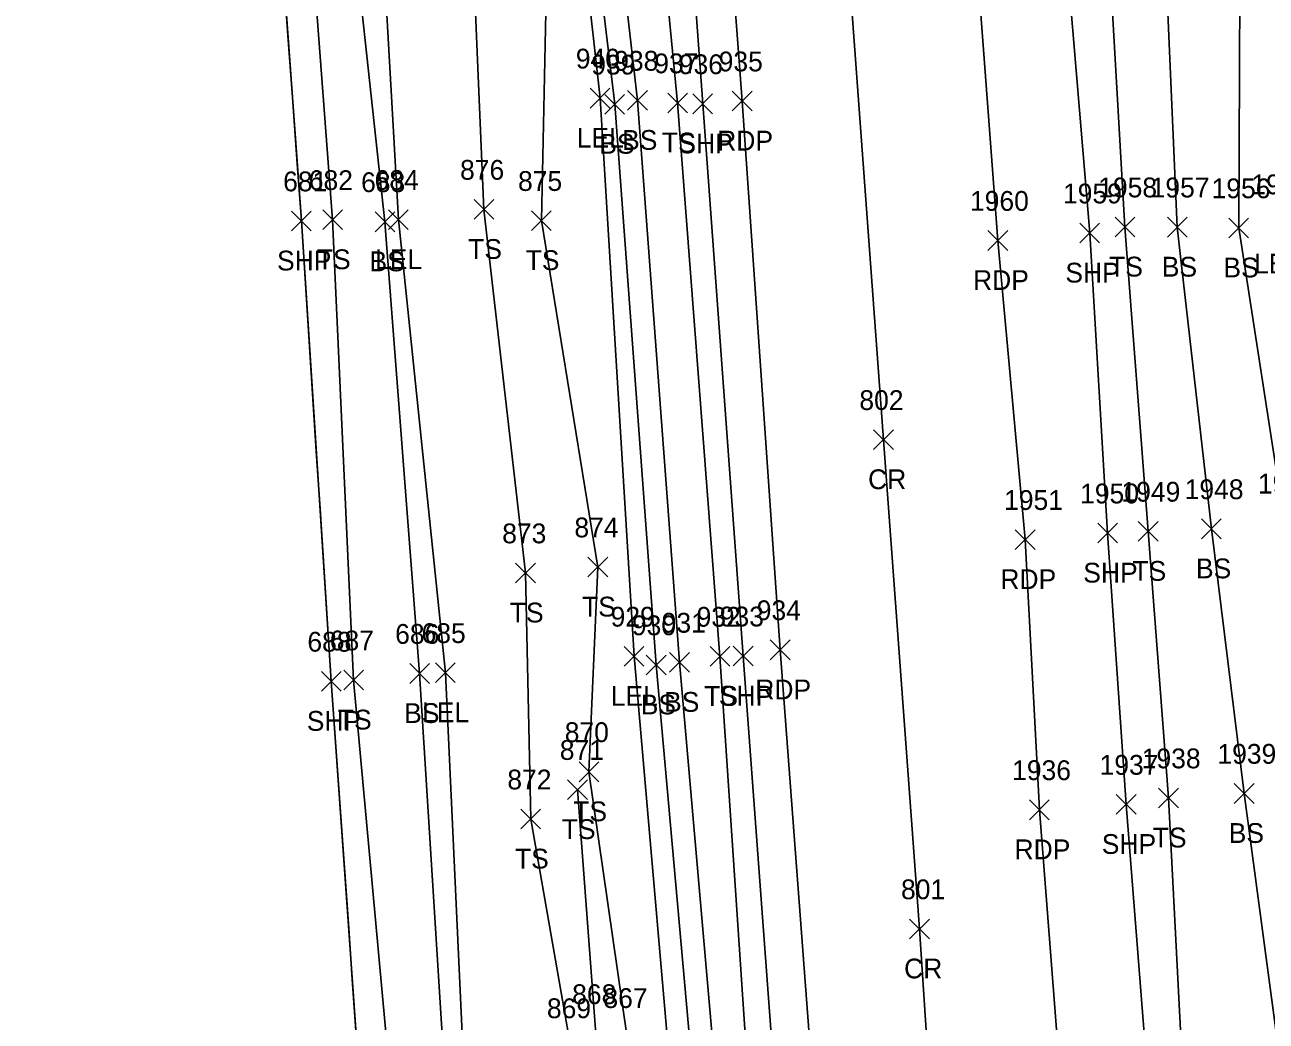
# Model space of a CAD drawing. Extents: x 1650221 to 1650634, y 244606 to 249996.
# Drawn here: x 1650345.8 to 1650471.2, y 245235.3 to 245336 of the extents above; entities that cross this region are included whole.
import ezdxf

# ---------------------------------------------------------------- set-up
doc = ezdxf.new("R2010")
doc.units = 0
for name, color, linetype in [('L_A', 7, 'Continuous'), ('L_I', 7, 'Continuous'), ('L_TIC', 7, 'Continuous'), ('LARO', 7, 'Continuous'), ('LELB', 7, 'Continuous'), ('LSOGP', 7, 'Continuous'), ('P_A', 7, 'Continuous'), ('P_I', 7, 'Continuous'), ('P_TIC', 7, 'Continuous'), ('PET', 7, 'Continuous'), ('PRC', 7, 'Continuous'), ('PSP', 7, 'Continuous')]:
    doc.layers.add(name, color=color, linetype=linetype)

msp = doc.modelspace()

# ---------------------------------------------------------------- linework, layer by layer
at = {"layer": 'L_TIC'}
for points in [[(1650402.92, 245327.57), (1650404.92, 245329.57)], [(1650404.92, 245327.57), (1650402.92, 245329.57)], [(1650404.4, 245326.96), (1650406.4, 245328.96)], [(1650406.4, 245326.96), (1650404.4, 245328.96)], [(1650406.71, 245327.35), (1650408.71, 245329.35)], [(1650408.71, 245327.35), (1650406.71, 245329.35)], [(1650410.76, 245327.09), (1650412.76, 245329.09)], [(1650412.76, 245327.09), (1650410.76, 245329.09)], [(1650391.18, 245316.33), (1650393.18, 245318.33)], [(1650393.18, 245316.33), (1650391.18, 245318.33)], [(1650375.89, 245315.29), (1650377.89, 245317.29)], [(1650377.89, 245315.29), (1650375.89, 245317.29)], [(1650381.18, 245315.08), (1650383.18, 245317.08)], [(1650383.18, 245315.08), (1650381.18, 245317.08)], [(1650382.54, 245315.3), (1650384.54, 245317.3)], [(1650384.54, 245315.3), (1650382.54, 245317.3)], [(1650396.99, 245315.2), (1650398.99, 245317.2)], [(1650398.99, 245315.2), (1650396.99, 245317.2)], [(1650455.97, 245314.55), (1650457.97, 245316.55)], [(1650457.97, 245314.55), (1650455.97, 245316.55)], [(1650461.26, 245314.54), (1650463.26, 245316.54)], [(1650463.26, 245314.54), (1650461.26, 245316.54)], [(1650467.47, 245314.46), (1650469.47, 245316.46)], [(1650469.47, 245314.46), (1650467.47, 245316.46)], [(1650458.32, 245283.8), (1650460.32, 245285.8)], [(1650460.32, 245283.8), (1650458.32, 245285.8)], [(1650464.71, 245284.05), (1650466.71, 245286.05)], [(1650466.71, 245284.05), (1650464.71, 245286.05)], [(1650395.39, 245279.59), (1650397.39, 245281.59)], [(1650397.39, 245279.59), (1650395.39, 245281.59)], [(1650402.69, 245280.19), (1650404.69, 245282.19)], [(1650404.69, 245280.19), (1650402.69, 245282.19)], [(1650406.36, 245271.17), (1650408.36, 245273.17)], [(1650408.36, 245271.17), (1650406.36, 245273.17)], [(1650408.59, 245270.3), (1650410.59, 245272.3)], [(1650410.59, 245270.3), (1650408.59, 245272.3)], [(1650410.95, 245270.56), (1650412.95, 245272.56)], [(1650412.95, 245270.56), (1650410.95, 245272.56)], [(1650415.04, 245271.16), (1650417.04, 245273.16)], [(1650417.04, 245271.16), (1650415.04, 245273.16)], [(1650384.68, 245269.43), (1650386.68, 245271.43)], [(1650386.68, 245269.43), (1650384.68, 245271.43)], [(1650387.29, 245269.51), (1650389.29, 245271.51)], [(1650389.29, 245269.51), (1650387.29, 245271.51)], [(1650378.01, 245268.77), (1650380.01, 245270.77)], [(1650380.01, 245268.77), (1650378.01, 245270.77)], [(1650401.8, 245259.5), (1650403.8, 245261.5)], [(1650403.8, 245259.5), (1650401.8, 245261.5)], [(1650400.64, 245257.7), (1650402.64, 245259.7)], [(1650402.64, 245257.7), (1650400.64, 245259.7)], [(1650460.37, 245256.85), (1650462.37, 245258.85)], [(1650462.37, 245256.85), (1650460.37, 245258.85)], [(1650468.02, 245257.31), (1650470.02, 245259.31)], [(1650470.02, 245257.31), (1650468.02, 245259.31)], [(1650395.91, 245254.72), (1650397.91, 245256.72)], [(1650397.91, 245254.72), (1650395.91, 245256.72)]]:
    msp.add_lwpolyline(points, dxfattribs=at)
at = {"layer": 'LARO'}
for points in [[(1650421.38, 244936.36), (1650423.35, 244936.27), (1650425.89, 244936.22), (1650434.3, 244938.37), (1650430.48, 244972), (1650427.02, 245018.52), (1650423.68, 245067.08), (1650420.77, 245123.48), (1650416.16, 245170.75), (1650416.29, 245170.75), (1650411.97, 245219.01), (1650407.36, 245272.17), (1650403.92, 245328.57), (1650398.22, 245379.76), (1650393.14, 245434.28), (1650390.04, 245478.89), (1650387.05, 245523.12), (1650386.02, 245551.2)], [(1650370.23, 245505.43), (1650373.27, 245470.75), (1650376.08, 245419.34), (1650380.61, 245367.82), (1650383.54, 245316.3), (1650388.29, 245270.51), (1650390.54, 245221.61), (1650394.38, 245168.62), (1650397.75, 245118.3), (1650404.08, 245063.51), (1650406.12, 245018.23), (1650409.93, 244966.8), (1650411.89, 244938.28)]]:
    msp.add_lwpolyline(points, dxfattribs=at)
at = {"layer": 'LELB'}
for points in [[(1650349.13, 245703.09), (1650351.39, 245660.59), (1650355.99, 245608.05), (1650358.47, 245560.96), (1650362.91, 245508.7), (1650365.76, 245471.06), (1650369.41, 245419.53), (1650373.04, 245367.18), (1650376.89, 245316.29), (1650379.01, 245269.77), (1650383.48, 245220.96), (1650387.1, 245168.26), (1650390.97, 245118.17), (1650394.99, 245063.19), (1650398.03, 245017.1), (1650401.94, 244967.25), (1650403.81, 244936.86), (1650407.34, 244889.23), (1650410.84, 244834.73), (1650414.52, 244785.95), (1650419.34, 244732.83), (1650422.93, 244682.99), (1650426.36, 244632.18), (1650427.51, 244611.7)], [(1650355.71, 245703.22), (1650358.45, 245660.47), (1650361.92, 245609.02), (1650362.95, 245561.76), (1650366.97, 245508.68), (1650370.97, 245471.38), (1650374.07, 245419.38), (1650376.64, 245367.03), (1650382.18, 245316.08), (1650385.68, 245270.43), (1650388.77, 245221.07), (1650390.77, 245168.69), (1650394.69, 245118), (1650401.29, 245063.19), (1650403.89, 245017.69), (1650406.99, 244966.96), (1650408.31, 244937.61), (1650413.12, 244889.16), (1650416.09, 244835.73), (1650420.51, 244786.1), (1650423.8, 244733.3), (1650426.51, 244682.57), (1650434.12, 244632.73), (1650437.01, 244612.78)], [(1650458.26, 244631.23), (1650456.79, 244671.65), (1650452.78, 244720.4), (1650448.37, 244766.08), (1650444.9, 244801.26), (1650441.62, 244837.94), (1650439.87, 244879.23), (1650437.68, 244923.9), (1650433.87, 244972.21), (1650429.49, 245017.89), (1650426.15, 245066.7), (1650422.69, 245123.12), (1650419.86, 245170.84), (1650416.52, 245219.13), (1650411.95, 245271.56), (1650407.71, 245328.35), (1650401.82, 245379.92), (1650396.45, 245433.97), (1650394.84, 245478.56), (1650392.49, 245522.5), (1650389.35, 245551.29), (1650385.12, 245588.75), (1650380.77, 245632.36), (1650373.15, 245685.41)], [(1650462.3, 244631.92), (1650459.1, 244671.43), (1650455.6, 244720.68), (1650451.8, 244765.92), (1650449.21, 244801.88), (1650446.61, 244838.72), (1650443.38, 244880.99), (1650440.04, 244922.8), (1650437.91, 244972.67), (1650433.82, 245018.12), (1650431.01, 245067.65), (1650425.84, 245123.86), (1650424.05, 245171.63), (1650419.6, 245218.92), (1650416.04, 245272.16), (1650411.76, 245328.09), (1650406.63, 245381.03), (1650402.95, 245434.27), (1650400.25, 245479.81), (1650396.41, 245522.79), (1650395.43, 245551.92), (1650392.44, 245589.61), (1650388.27, 245633.5), (1650384.04, 245685.26)], [(1650489.71, 244991.22), (1650489.69, 245009.71), (1650486.09, 245047.64), (1650483.87, 245079.25), (1650480.92, 245116.18), (1650479.42, 245140.42), (1650476.29, 245187.3), (1650474, 245221.05), (1650469.02, 245258.31), (1650465.71, 245285.05), (1650462.26, 245315.54), (1650460.48, 245356.55), (1650462.16, 245378.82), (1650455.67, 245427.55), (1650451.48, 245462.76), (1650449.79, 245512.44), (1650449.11, 245548.12), (1650443.42, 245590.47), (1650442.32, 245632.05), (1650435.43, 245684.43)], [(1650471.05, 245115.28), (1650468.74, 245140.33), (1650464.89, 245185.98), (1650463.25, 245221.34), (1650461.37, 245257.85), (1650459.32, 245284.8), (1650456.97, 245315.55), (1650454.6, 245356.59), (1650452.98, 245378.54), (1650450.43, 245426.58), (1650446.12, 245463.42), (1650443.52, 245512.09), (1650441.71, 245548.12), (1650438.37, 245589.38), (1650434.29, 245631.65), (1650429.68, 245683.37)], [(1650493.15, 245007.74), (1650488.13, 245047.67), (1650486.59, 245079.09), (1650485.35, 245117.44), (1650483.97, 245140), (1650485.34, 245188.31), (1650482.43, 245221.37), (1650477.25, 245258), (1650473.1, 245285.62), (1650468.47, 245315.46), (1650468.65, 245355.64), (1650472.97, 245377.88), (1650463.98, 245429.04), (1650464.45, 245462.11), (1650460.79, 245514.67), (1650465.46, 245547.92), (1650447.43, 245596.3), (1650450.46, 245632.25)], [(1650417.42, 245170.71), (1650414.29, 245218.92), (1650409.59, 245271.3), (1650405.4, 245327.96), (1650399.15, 245380.06), (1650394.45, 245434.24), (1650392.17, 245479.25), (1650388.55, 245523.47), (1650387.04, 245550.93), (1650374.54, 245599.04)], [(1650411.56, 245100.31), (1650410.98, 245134.62), (1650407.62, 245167.58), (1650401.15, 245195.95), (1650400.96, 245232.6), (1650396.91, 245255.72), (1650396.39, 245280.59), (1650392.18, 245317.33), (1650390.56, 245355.55), (1650386.02, 245389.39), (1650383.37, 245430.51), (1650379.67, 245462.51), (1650379.96, 245467.43), (1650380, 245489.06), (1650377.56, 245510.96), (1650374.72, 245546.33), (1650373.24, 245560.96), (1650373.27, 245589.26)], [(1650417.99, 245100.65), (1650416.66, 245133.49), (1650414.16, 245167.69), (1650410.2, 245197), (1650406.67, 245233.63), (1650402.8, 245260.5), (1650403.69, 245281.19), (1650397.99, 245316.2), (1650398.84, 245356.67), (1650390.42, 245389.46), (1650390.16, 245432.43), (1650385.39, 245460.04), (1650384.98, 245466.18), (1650387.77, 245488.08), (1650384.3, 245517.36), (1650381.95, 245546.8), (1650375.57, 245561.13), (1650373.27, 245589.26)], [(1650438.88, 244749.14), (1650437.59, 244767.7), (1650432.8, 244801.89), (1650429.64, 244835.41), (1650428.64, 244877.68), (1650423.48, 244923.01), (1650423.35, 244936.27), (1650423.08, 244949.37), (1650423.3, 244968.5), (1650419.67, 244981.26), (1650420.71, 245016.76), (1650415.5, 245052.76), (1650413.6, 245072.27), (1650415.28, 245100.97), (1650413.57, 245134.68), (1650410.33, 245167.49), (1650406.45, 245196.84), (1650403.51, 245234.02), (1650401.64, 245258.7)]]:
    msp.add_lwpolyline(points, dxfattribs=at)
at = {"layer": 'LSOGP'}
msp.add_lwpolyline([(1650371.91, 245341.16), (1650372.37, 245334.91), (1650372.82, 245328.66), (1650373.28, 245322.41), (1650373.73, 245316.16), (1650374.11, 245310.34), (1650374.48, 245304.53), (1650374.86, 245298.71), (1650375.24, 245292.9), (1650375.62, 245287.08), (1650375.99, 245281.27), (1650376.37, 245275.45), (1650376.75, 245269.64), (1650377.18, 245263.52), (1650377.61, 245257.4), (1650378.05, 245251.28), (1650378.48, 245245.16), (1650378.91, 245239.03), (1650379.35, 245232.91)], dxfattribs=at)
at = {"layer": 'P_TIC'}
for points in [[(1650413.3, 245327), (1650415.3, 245329)], [(1650415.3, 245327), (1650413.3, 245329)], [(1650417.28, 245327.28), (1650419.28, 245329.28)], [(1650419.28, 245327.28), (1650417.28, 245329.28)], [(1650372.73, 245315.16), (1650374.73, 245317.16)], [(1650374.73, 245315.16), (1650372.73, 245317.16)], [(1650443.13, 245313.19), (1650445.13, 245315.19)], [(1650445.13, 245313.19), (1650443.13, 245315.19)], [(1650452.41, 245313.94), (1650454.41, 245315.94)], [(1650454.41, 245313.94), (1650452.41, 245315.94)], [(1650431.57, 245293.06), (1650433.57, 245295.06)], [(1650433.57, 245293.06), (1650431.57, 245295.06)], [(1650445.89, 245282.96), (1650447.89, 245284.96)], [(1650447.89, 245282.96), (1650445.89, 245284.96)], [(1650454.22, 245283.62), (1650456.22, 245285.62)], [(1650456.22, 245283.62), (1650454.22, 245285.62)], [(1650421.12, 245271.82), (1650423.12, 245273.82)], [(1650423.12, 245271.82), (1650421.12, 245273.82)], [(1650417.38, 245271.19), (1650419.38, 245273.19)], [(1650419.38, 245271.19), (1650417.38, 245273.19)], [(1650375.75, 245268.64), (1650377.75, 245270.64)], [(1650377.75, 245268.64), (1650375.75, 245270.64)], [(1650447.32, 245255.66), (1650449.32, 245257.66)], [(1650449.32, 245255.66), (1650447.32, 245257.66)], [(1650456.1, 245256.2), (1650458.1, 245258.2)], [(1650458.1, 245256.2), (1650456.1, 245258.2)], [(1650435.21, 245243.62), (1650437.21, 245245.62)], [(1650437.21, 245243.62), (1650435.21, 245245.62)]]:
    msp.add_lwpolyline(points, dxfattribs=at)
at = {"layer": 'PET'}
for points in [[(1650468.61, 244633.66), (1650465.16, 244679.18), (1650461.18, 244730.39), (1650457.78, 244777.29), (1650455.76, 244806.01), (1650453.3, 244838.79), (1650450.33, 244880.04), (1650447.22, 244922.32), (1650443.48, 244972.73), (1650440.49, 245018.18), (1650436.73, 245069.12), (1650432.63, 245123.79), (1650429.44, 245172.68), (1650426.2, 245218.76), (1650422.12, 245272.82), (1650418.28, 245328.28), (1650414.28, 245381.59), (1650410.42, 245434.18), (1650407.03, 245480.26), (1650404.25, 245522.13), (1650401.81, 245552.98), (1650399.16, 245589.27), (1650395.97, 245634.45), (1650392.36, 245685.55)], [(1650458.15, 245114.32), (1650456.62, 245139.84), (1650453.42, 245185.54), (1650451.1, 245220.97), (1650448.32, 245256.66), (1650446.89, 245283.96), (1650444.13, 245314.19), (1650440.98, 245355.92), (1650439.55, 245378.58), (1650435.64, 245425.9), (1650433.13, 245463.89), (1650429.51, 245512.19), (1650427.14, 245547.69), (1650424.3, 245587.11), (1650421.18, 245630.65), (1650417.91, 245681.78)]]:
    msp.add_lwpolyline(points, dxfattribs=at)
at = {"layer": 'PRC'}
msp.add_lwpolyline([(1650447.57, 245085.81), (1650443.28, 245144.22), (1650439.84, 245189.25), (1650436.21, 245244.62), (1650432.57, 245294.06), (1650428.87, 245344.44), (1650424.91, 245397.45), (1650422.06, 245440.46), (1650418.2, 245485.2), (1650414.81, 245534.63), (1650412.73, 245565.5), (1650409.49, 245611.37), (1650407.05, 245649.82), (1650403.01, 245697.04)], dxfattribs=at)
at = {"layer": 'PSP'}
for points in [[(1650345.78, 245703.18), (1650348.63, 245659.65), (1650352.24, 245608.27), (1650356.14, 245560.76), (1650359.83, 245508.67), (1650362.71, 245470.35), (1650366.37, 245419.55), (1650370.09, 245366.17), (1650373.73, 245316.16), (1650376.75, 245269.64), (1650380.21, 245220.67), (1650384.07, 245168.16), (1650387.54, 245117.86), (1650391.85, 245063.26), (1650394.9, 245017.42), (1650398.56, 244967.17), (1650400.8, 244936.49), (1650404.42, 244889.02), (1650408.47, 244833.97), (1650411.77, 244786.13), (1650415.79, 244732.16), (1650419.27, 244682.87), (1650423.02, 244632.43), (1650424.78, 244611.26)], [(1650464.84, 244632.07), (1650461.81, 244671.31), (1650457.94, 244720.75), (1650454.77, 244765.54), (1650451.99, 244802.46), (1650449.34, 244838.71), (1650446.5, 244879.72), (1650443.46, 244922.98), (1650439.98, 244973.19), (1650436.37, 245018.02), (1650433.26, 245068.28), (1650429.09, 245123.84), (1650425.59, 245171.99), (1650422.33, 245218.99), (1650418.38, 245272.19), (1650414.3, 245328), (1650410.4, 245381.3), (1650406.52, 245434.23), (1650403.48, 245480), (1650400.24, 245522.79), (1650398.25, 245552.46), (1650395.41, 245589.43), (1650392.23, 245633.8), (1650388.44, 245685.1)], [(1650467.35, 245115.19), (1650465.66, 245140.38), (1650462.4, 245185.76), (1650459.93, 245221.23), (1650457.1, 245257.2), (1650455.22, 245284.62), (1650453.41, 245314.94), (1650449.96, 245356.27), (1650448.46, 245377.97), (1650444.62, 245426.85), (1650442.19, 245463.43), (1650438.55, 245512.23), (1650436.23, 245548.05), (1650433.37, 245588.35), (1650430.25, 245631.19), (1650426.21, 245683.01)]]:
    msp.add_lwpolyline(points, dxfattribs=at)

# ---------------------------------------------------------------- texts
at = {"layer": 'L_A'}
for s, p in [('LEL', (1650401.56, 245323.57)), ('BS', (1650403.84, 245322.96)), ('BS', (1650406.15, 245323.35)), ('TS', (1650410.17, 245323.09)), ('TS', (1650390.59, 245312.33)), ('TS', (1650375.3, 245311.29)), ('BS', (1650380.62, 245311.08)), ('LEL', (1650381.18, 245311.3)), ('TS', (1650396.4, 245311.2)), ('TS', (1650455.37, 245310.55)), ('BS', (1650460.7, 245310.54)), ('BS', (1650466.92, 245310.46)), ('LER', (1650470.02, 245310.86)), ('TS', (1650457.73, 245279.8)), ('BS', (1650464.15, 245280.05)), ('TS', (1650394.8, 245275.59)), ('TS', (1650402.1, 245276.19)), ('LEL', (1650405, 245267.17)), ('BS', (1650410.39, 245266.56)), ('TS', (1650414.45, 245267.16)), ('BS', (1650384.12, 245265.43)), ('LEL', (1650385.93, 245265.51)), ('BS', (1650408.03, 245266.3)), ('TS', (1650377.42, 245264.77)), ('TS', (1650401.21, 245255.5)), ('TS', (1650400.05, 245253.7)), ('TS', (1650459.78, 245252.85)), ('BS', (1650467.46, 245253.31)), ('TS', (1650395.32, 245250.72))]:
    msp.add_text(s, height=2, dxfattribs=at).set_placement(p)
at = {"layer": 'L_I'}
for s, p in [('940', (1650401.47, 245331.57)), ('939', (1650403.03, 245330.96)), ('938', (1650405.35, 245331.35)), ('937', (1650409.4, 245331.09)), ('682', (1650374.48, 245319.29)), ('684', (1650381.13, 245319.3)), ('876', (1650389.77, 245320.33)), ('875', (1650395.63, 245319.2)), ('683', (1650379.77, 245319.08)), ('1958', (1650454.27, 245318.55)), ('1957', (1650459.57, 245318.54)), ('1956', (1650465.73, 245318.46)), ('1955', (1650469.75, 245318.86)), ('1948', (1650463.01, 245288.05)), ('1947', (1650470.41, 245288.62)), ('1949', (1650456.62, 245287.8)), ('874', (1650401.33, 245284.19)), ('873', (1650394.03, 245283.59)), ('929', (1650404.99, 245275.17)), ('930', (1650407.14, 245274.3)), ('931', (1650410.15, 245274.56)), ('932', (1650413.68, 245275.16)), ('687', (1650376.6, 245272.77)), ('686', (1650383.21, 245273.43)), ('685', (1650385.88, 245273.51)), ('870', (1650400.35, 245263.5)), ('871', (1650399.85, 245261.7)), ('1938', (1650458.67, 245260.85)), ('1939', (1650466.32, 245261.31)), ('872', (1650394.55, 245258.72)), ('868', (1650401.1, 245237.02)), ('867', (1650404.26, 245236.63)), ('869', (1650398.55, 245235.6))]:
    msp.add_text(s, height=2, dxfattribs=at).set_placement(p)
at = {"layer": 'P_A'}
for s, p in [('SHP', (1650411.84, 245323)), ('RDP', (1650415.76, 245323.28)), ('SHP', (1650371.27, 245311.16)), ('RDP', (1650441.62, 245309.19)), ('SHP', (1650450.95, 245309.94)), ('CR', (1650431.01, 245289.06)), ('SHP', (1650452.76, 245279.62)), ('RDP', (1650444.38, 245278.96)), ('RDP', (1650419.61, 245267.82)), ('SHP', (1650415.92, 245267.19)), ('SHP', (1650374.28, 245264.64)), ('RDP', (1650445.81, 245251.66)), ('SHP', (1650454.63, 245252.2)), ('CR', (1650434.65, 245239.62))]:
    msp.add_text(s, height=2, dxfattribs=at).set_placement(p)
at = {"layer": 'P_I'}
for s, p in [('936', (1650411.88, 245331)), ('935', (1650415.91, 245331.28)), ('681', (1650371.89, 245319.16)), ('1959', (1650450.71, 245317.94)), ('1960', (1650441.31, 245317.19)), ('802', (1650430.13, 245297.06)), ('1951', (1650444.76, 245286.96)), ('1950', (1650452.44, 245287.62)), ('934', (1650419.76, 245275.82)), ('933', (1650416.02, 245275.19)), ('688', (1650374.34, 245272.64)), ('1936', (1650445.57, 245259.66)), ('1937', (1650454.41, 245260.2)), ('801', (1650434.34, 245247.62))]:
    msp.add_text(s, height=2, dxfattribs=at).set_placement(p)

doc.saveas('drawing.dxf')
